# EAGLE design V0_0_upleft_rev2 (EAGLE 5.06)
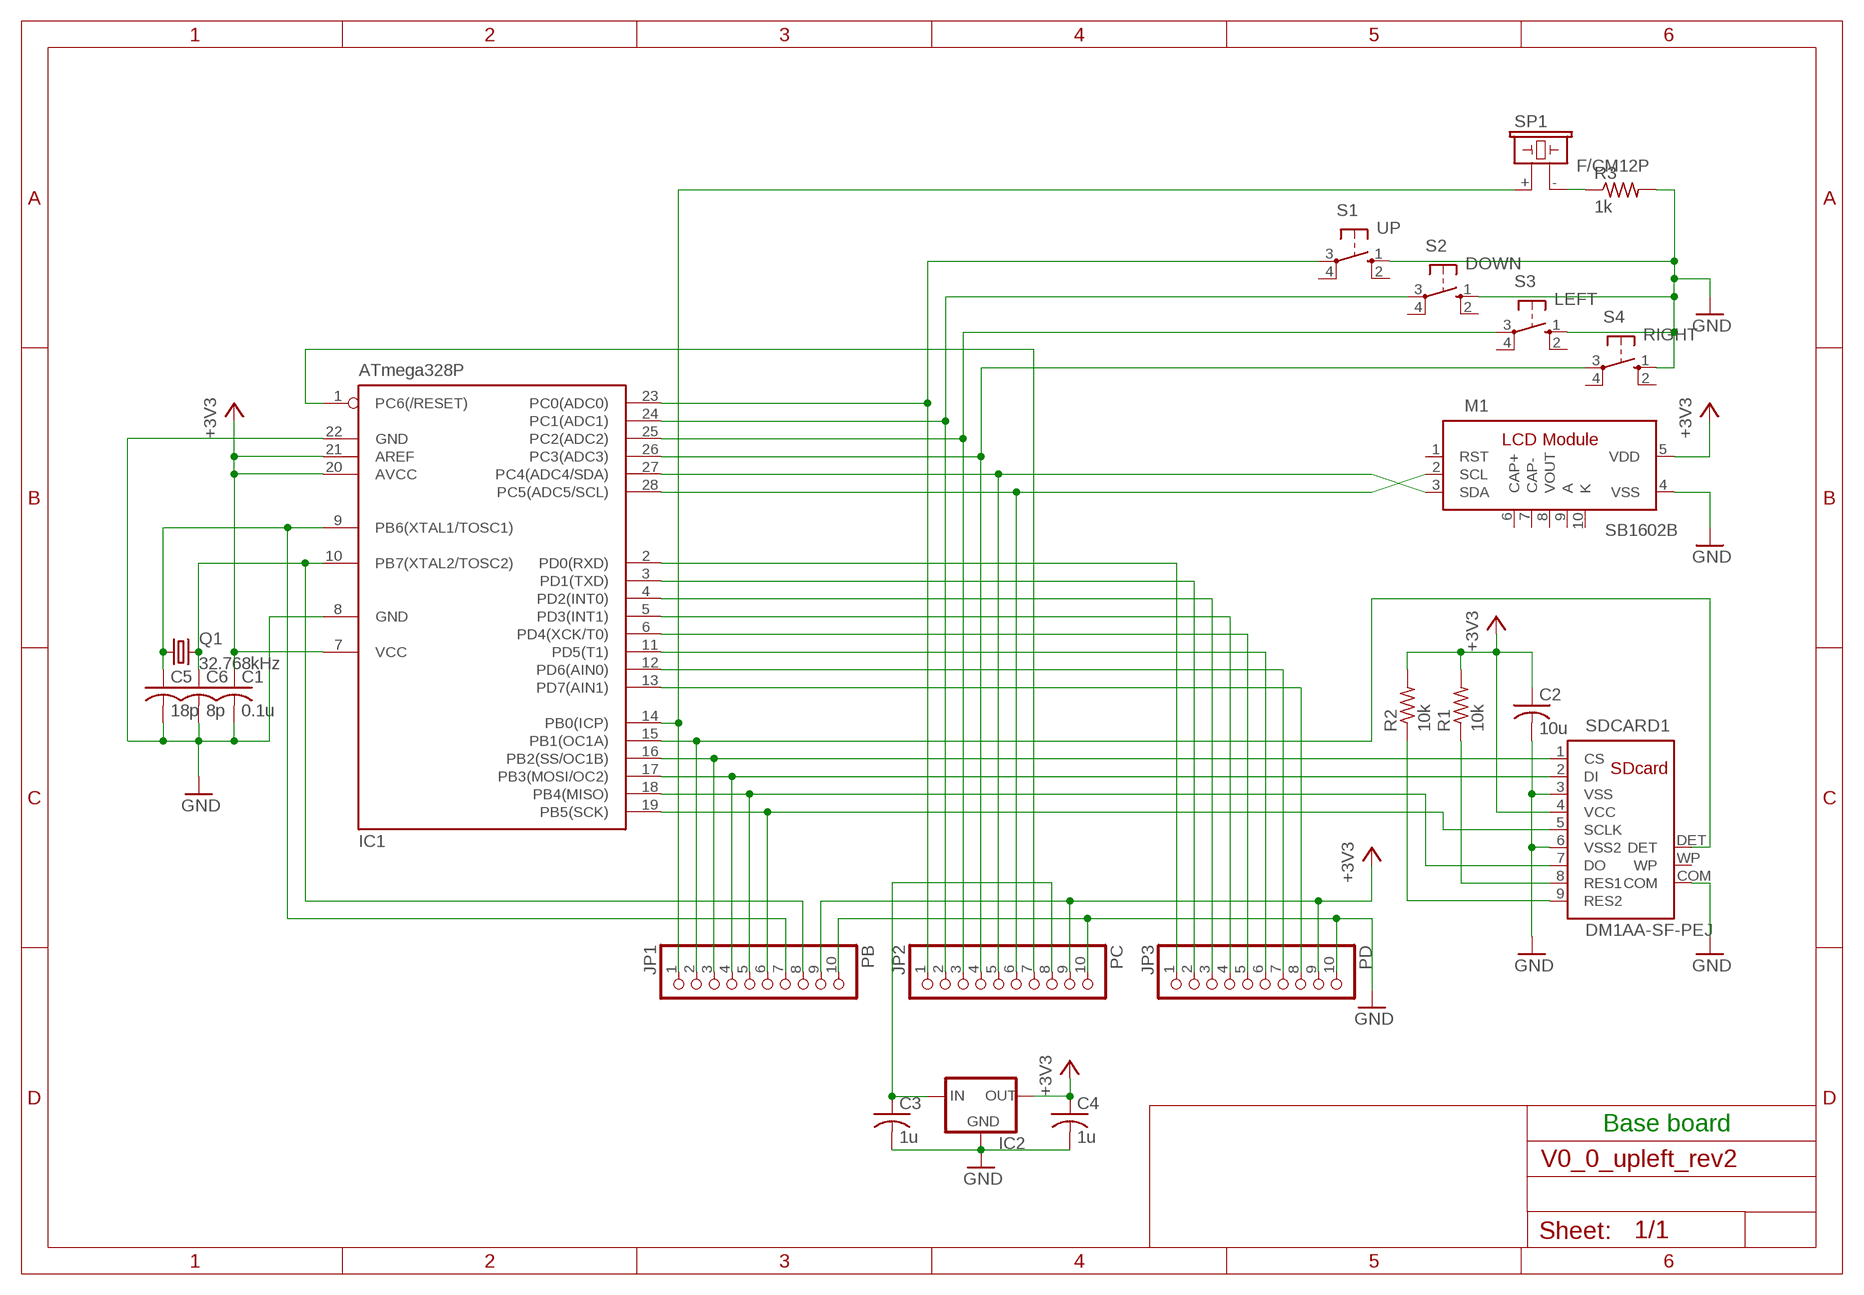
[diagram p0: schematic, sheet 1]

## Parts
C1  0.1u  C-US025-024X044  [C025-024X044]
C2  10u  C-US025-024X044  [C025-024X044]
C3  1u  C-US025-024X044  [C025-024X044]
C4  1u  C-US025-024X044  [C025-024X044]
C5  18p  C-US025-024X044  [C025-024X044]
C6  8p  C-US025-024X044  [C025-024X044]
IC1  ATmega328P  MEGA8-P  [DIL28-3]
IC2  XC63FPL  [TO92]
JP1  PB  PINHD-1X10  [1X10]
JP2  PC  PINHD-1X10  [1X10]
JP3  PD  PINHD-1X10  [1X10]
M1  SB1602B  [SB1602B]
Q1  32.768kHz  CRYSTALTC26H  [TC26H]
R1  10k  R-US_0204/5  [0204/5]
R2  10k  R-US_0204/5  [0204/5]
R3  1k  R-US_0204/5  [0204/5]
S1  UP  10-XX  [B3F-10XX]
S2  DOWN  10-XX  [B3F-10XX]
S3  LEFT  10-XX  [B3F-10XX]
S4  RIGHT  10-XX  [B3F-10XX]
SDCARD1  DM1AA-SF-PEJ  [DM1AA]
SP1  F/CM12P  [F/CM12P]

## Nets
+3V3: C1.1 C2.1 C4.1 IC1.7(VCC) IC1.20(AVCC) IC1.21(AREF) IC2.3(OUT) JP1.9 JP2.9 JP3.9 M1.5(VDD) R1.2 R2.2 SDCARD1.4(VCC)
GND: C1.2 C2.2 C3.2 C4.2 C5.2 C6.2 IC1.8(GND) IC1.22(GND) IC2.2(GND) JP1.10 JP2.10 JP3.10 M1.4(VSS) R3.2 S1.1(S) S2.1(S) S3.1(S) S4.1(S) SDCARD1.3(VSS) SDCARD1.6(VSS2) SDCARD1.COM
N$1: IC1.16(PB2(SS/OC1B)) JP1.3 SDCARD1.1(CS)
N$2: IC1.17(PB3(MOSI/OC2)) JP1.4 SDCARD1.2(DI)
N$3: IC1.18(PB4(MISO)) JP1.5 SDCARD1.7(DO)
N$4: IC1.19(PB5(SCK)) JP1.6 SDCARD1.5(SCLK)
N$5: IC1.27(PC4(ADC4/SDA)) JP2.5 M1.3(SDA)
N$6: IC1.28(PC5(ADC5/SCL)) JP2.6 M1.2(SCL)
N$7: IC1.2(PD0(RXD)) JP3.1
N$8: IC1.3(PD1(TXD)) JP3.2
N$9: R1.1 SDCARD1.8(RES1)
N$10: R2.1 SDCARD1.9(RES2)
N$11: IC1.4(PD2(INT0)) JP3.3
N$12: IC1.5(PD3(INT1)) JP3.4
N$13: IC1.6(PD4(XCK/T0)) JP3.5
N$14: IC1.11(PD5(T1)) JP3.6
N$15: IC1.12(PD6(AIN0)) JP3.7
N$16: IC1.13(PD7(AIN1)) JP3.8
N$17: R3.1 SP1.-
N$18: IC1.23(PC0(ADC0)) JP2.1 S1.3(P)
N$19: IC1.24(PC1(ADC1)) JP2.2 S2.3(P)
N$20: IC1.25(PC2(ADC2)) JP2.3 S3.3(P)
N$21: IC1.26(PC3(ADC3)) JP2.4 S4.3(P)
N$22: IC1.14(PB0(ICP)) JP1.1 SP1.+
N$23: IC1.15(PB1(OC1A)) JP1.2 SDCARD1.DET
N$24: C5.1 IC1.9(PB6(XTAL1/TOSC1)) JP1.7 Q1.1
N$26: IC1.1(PC6(/RESET)) JP2.7
N$27: C3.1 IC2.1(IN) JP2.8
N$28: C6.1 IC1.10(PB7(XTAL2/TOSC2)) JP1.8 Q1.2
Unconnected: M1.1(RST) M1.6(CAP+) M1.7(CAP-) M1.8(VOUT) S1.2(S1) S1.4(P1) S2.2(S1) S2.4(P1) S3.2(S1) S3.4(P1) S4.2(S1) S4.4(P1) SDCARD1.WP

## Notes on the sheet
- Base board

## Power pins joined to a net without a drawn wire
A: M1.9(A)
K: M1.10(K)

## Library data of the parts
C1-C6 = rcl:C-US: CAPACITOR, American symbol
IC1 = atmel:MEGA8-P: MICROCONTROLLER 8 Kbytes FLASH, 1 kbytes SRAM, 512 bytes EEPROM, USART, 4-channel 10 bit ADC, 2-channel 8 bit ADC Pin compatible with Atmega48, ATMega88, ATMega168 Source: avr.lbr
IC2 = v-reg:XC63FP: Positiv Voltage Regulators www.torex.co.jp/english/product/pro02/pdf/0201_xc62fp.pdf
JP1-JP3 = pinhead:PINHD-1X10: PIN HEADER
M1 = TOG:SB1602B: Strawberry Linux Co.,Ltd. I2C LCD Module Controler: ST7032i
Q1 = crystal:CRYSTAL: CRYSTAL
R1-R3 = rcl:R-US_: RESISTOR, American symbol
S1-S4 = switch-omron:10-XX: OMRON SWITCH
SDCARD1 = TOG:DM1AA-SF-PEJ: SDcard connector HIROSE
SP1 = buzzer:F/CM12P: BUZZER

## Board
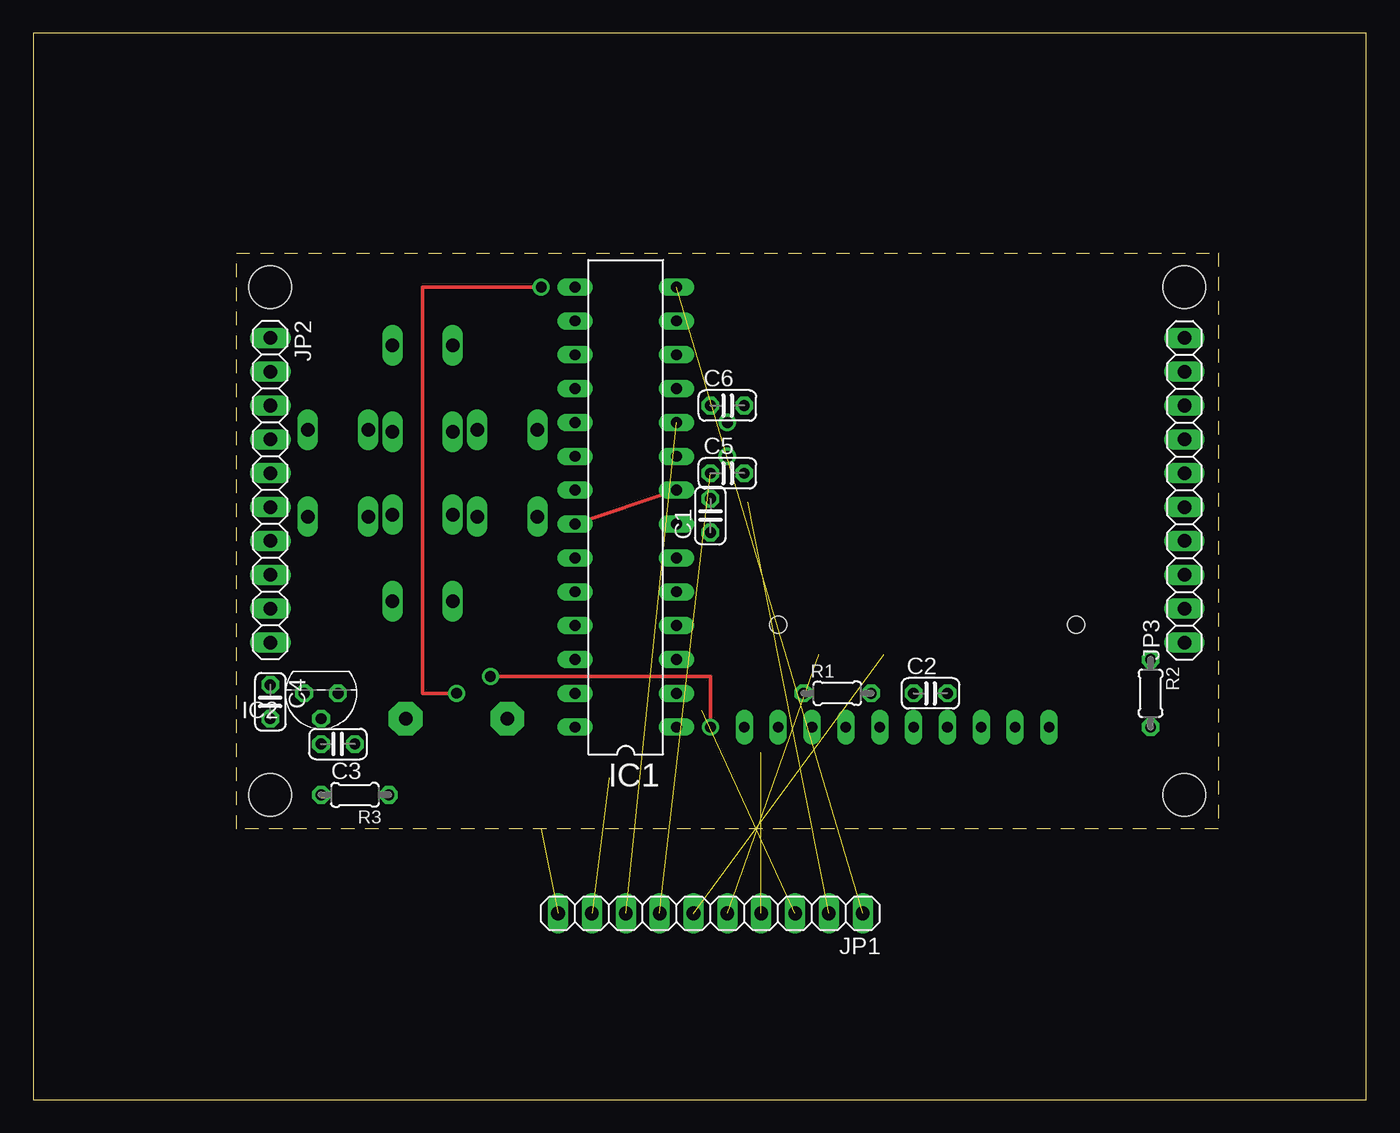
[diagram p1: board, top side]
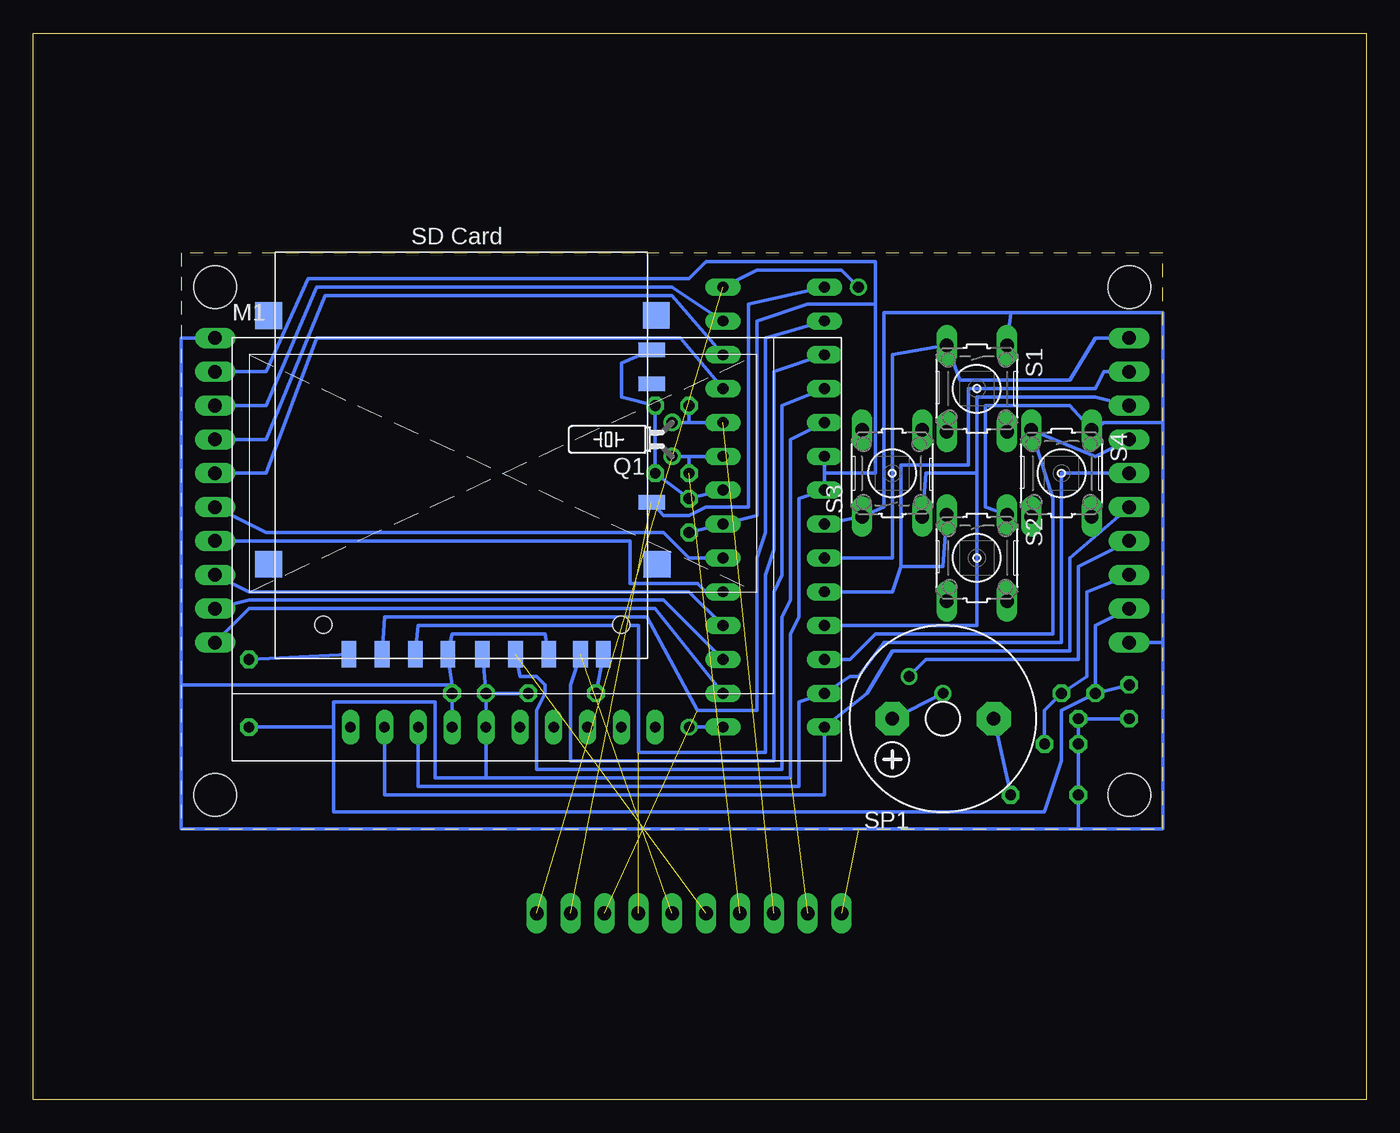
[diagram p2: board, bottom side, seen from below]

Size 100 x 80 mm. Coordinates in mm from the lower left corner, seen from the top.
Outline: 0,0 100,0 100,80 0,80 0,0
Outline: 15.24,63.5 88.9,63.5 88.9,20.32 15.24,20.32 15.24,63.5
Copper layers (1*16): Top 0.035mm / dielectric 1.5mm / Bottom 0.035mm
Design rules "default": minimum track width 10mil, minimum drill 24mil, track to track 8mil, track to pad 8mil, pad to pad 8mil, via to via 8mil, smd to smd 8mil, copper to edge 40mil, drill to drill 8mil, minimum pad ring 10mil, minimum via ring 8mil, stop-mask expansion 4mil, vias tented up to drill 0mil, thermal gap 10mil
Holes 3.2 mm at 17.78,60.96 86.36,60.96 86.36,22.86 17.78,22.86

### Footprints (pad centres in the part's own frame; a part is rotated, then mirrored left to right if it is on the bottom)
C025-024X044 = drill 0.813 octagon: 1 -1.27,0; 2 1.27,0
DIL28-3 = drill 0.813 long: 1 -16.51,-3.81; 2 -13.97,-3.81; 3 -11.43,-3.81; 4 -8.89,-3.81; 5 -6.35,-3.81; 6 -3.81,-3.81; 7 -1.27,-3.81; 8 1.27,-3.81; 9 3.81,-3.81; 10 6.35,-3.81; 11 8.89,-3.81; 12 11.43,-3.81; 13 13.97,-3.81; 14 16.51,-3.81; 15 16.51,3.81; 16 13.97,3.81; 17 11.43,3.81; 18 8.89,3.81; 19 6.35,3.81; 20 3.81,3.81; 21 1.27,3.81; 22 -1.27,3.81; 23 -3.81,3.81; 24 -6.35,3.81; 25 -8.89,3.81; 26 -11.43,3.81; 27 -13.97,3.81; 28 -16.51,3.81
TO92 = drill 0.813 octagon: 1 -1.27,0; 2 0,1.905; 3 1.27,0
1X10 = drill 1.016 long: 1 -11.43,0; 2 -8.89,0; 3 -6.35,0; 4 -3.81,0; 5 -1.27,0; 6 1.27,0; 7 3.81,0; 8 6.35,0; 9 8.89,0; 10 11.43,0
SB1602B = drill 0.8 long: 1 -13.97,-12.7; 2 -11.43,-12.7; 3 -8.89,-12.7; 4 -6.35,-12.7; 5 -3.81,-12.7; 6 -1.27,-12.7; 7 1.27,-12.7; 8 3.81,-12.7; 9 6.35,-12.7; 10 8.89,-12.7
TC26H = drill 0.813 round: 1 -1.27,0; 2 1.27,0
0204/5 = drill 0.813 octagon: 1 -2.54,0; 2 2.54,0
B3F-10XX = drill 1.016 long: 1 -3.251,2.261; 2 3.251,2.261; 3 -3.251,-2.261; 4 3.251,-2.261
DM1AA = smd 1.1 x 2: 1 3.98,14.22; 2 1.49,14.22; 3 -0.95,14.22; 4 -3.54,14.22; 5 -6.03,14.22; 6 -8.52,14.22; 7 -10.91,14.22; 8 -12.615,14.22; 9 6.47,14.22 | smd 2 x 1.1: COM -16.24,-8.62; DET -16.24,2.81; WP -16.24,-6.08 | smd 2.007 x 2.007: FG -16.64,7.455; P$13 12.5,7.455; P$14 12.5,-11.19; P$15 -16.59,-11.21 | hole 1.3: 8.39,12; -13.97,12
F/CM12P = drill 1.016 pad 2.54 octagon: + 3.81,0; - -3.81,0

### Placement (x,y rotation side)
C1  50.8,43.81 90 top
C2  67.31,30.48 0 top
C3  22.86,26.67 180 top
C4  17.78,29.84 270 top
C5  52.07,46.99 0 top
C6  52.07,52.07 0 top
IC1  44.45,44.45 90 top
IC2  21.59,30.48 180 top
JP1  50.8,13.97 180 top
JP2  17.78,45.72 270 top
JP3  86.36,45.72 90 top
M1  62.23,40.64 0 bottom
Q1  52.07,49.53 90 bottom
R1  60.33,30.48 0 top
R2  83.82,30.48 270 top
R3  24.13,22.86 180 top
S1  29.21,53.34 270 bottom
S2  29.21,40.64 270 bottom
S3  35.56,46.99 90 bottom
S4  22.86,46.99 270 bottom
SDCARD1  69.85,47.62 180 bottom
SP1  31.75,28.57 180 bottom

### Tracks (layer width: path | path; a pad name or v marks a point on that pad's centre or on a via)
+3V3  (1 unrouted)
  Bottom 0.254: IC2.3 20.32,35.56 JP2.9 | IC2.3 C4.1 | C1.1 IC1.7 45.72,43.81 45.72,58.42 41.91,59.69 36.83,59.69 | 40.64,46.99 IC1.21 42.55,45.09 42.55,36.2 43.18,34.92 43.18,24.13 66.04,24.13 | 40.64,46.99 IC1.20 | C2.1 SDCARD1.4 | C2.1 M1.5 66.04,24.13 | 36.83,59.69 36.83,46.99 40.64,46.99 | 66.04,24.13 69.85,24.13 69.85,29.84 77.47,29.84 77.47,27.94 | 77.47,27.94 77.47,21.59 24.13,21.59 22.86,25.4 22.86,29.21 IC2.3 | C2.1 R1.2 | 77.47,27.94 R2.2 | JP3.9 82.55,54.61 79.38,61.59 50.8,61.59 49.53,62.87 36.83,62.87 36.83,59.69
GND  (1 unrouted)
  Top 0.254: IC1.22 IC1.8
  Bottom 0.254: 88.9,31.11 88.9,20.32 38.1,20.32 21.59,20.32 | 88.9,31.11 88.9,57.15 JP3.10 | 21.59,20.32 15.24,20.32 15.24,34.29 | 15.24,34.29 15.24,50.8 | 15.24,50.8 15.24,59.05 26.67,59.05 | 26.67,59.05 36.2,59.05 36.2,44.45 S3.1 IC1.22 | 26.67,59.05 S1.1 | 15.24,50.8 19.68,50.8 S4.1 22.23,52.07 28.57,52.07 28.57,44.45 S2.1 | C4.2 IC2.2 C3.2 21.59,24.13 | 21.59,20.32 21.59,24.13 | 15.24,34.29 JP2.10 | IC1.8 C1.2 C5.2 C6.2 55.88,52.7 55.88,55.24 SDCARD1.COM | SDCARD1.6 61.59,34.92 68.58,34.92 SDCARD1.3 68.58,31.11 | M1.4 C2.2 68.58,31.11 | 88.9,31.11 68.58,31.11 | 21.59,24.13 R3.2
N$1  (1 unrouted)
  Bottom 0.254: IC1.16 45.09,57.15 45.09,42.55 45.72,40.64 45.72,29.21 50.16,29.21 53.98,36.2 73.66,36.2 SDCARD1.1
N$2  (1 unrouted)
  Bottom 0.254: IC1.17 44.45,54.61 44.45,41.27 45.09,39.37 45.09,26.04 54.61,26.04 54.61,35.56 71.12,35.56 SDCARD1.2
N$3  (1 unrouted)
  Bottom 0.254: IC1.18 43.81,52.07 43.81,39.37 44.45,38.1 44.45,25.4 59.69,25.4 59.69,31.11 SDCARD1.7
N$4  (1 unrouted)
  Bottom 0.254: IC1.19 43.18,49.53 43.18,37.47 43.81,36.2 43.81,24.77 62.23,24.77 62.23,29.21 61.59,30.48 61.59,31.11 62.23,31.75 63.5,31.75 SDCARD1.5
N$5
  Bottom 0.254: JP2.5 22.86,46.99 22.86,34.29 36.2,34.29 38.1,31.75 38.73,31.75 IC1.27 42.55,29.84 42.55,23.5 71.12,23.5 M1.3
N$6
  Bottom 0.254: JP2.6 22.23,40.64 22.23,33.66 35.56,33.66 37.47,30.48 IC1.28 40.64,22.86 73.66,22.86 M1.2
N$7
  Bottom 0.254: IC1.2 53.34,36.83 83.82,36.83 JP3.1
N$8
  Bottom 0.254: IC1.3 52.7,37.47 83.82,37.47 JP3.2
N$9
  Bottom 0.254: R1.1 SDCARD1.8
N$10
  Bottom 0.254: SDCARD1.9 R2.1
N$11
  Bottom 0.254: IC1.4 50.8,38.1 83.82,38.1 JP3.3
N$12
  Bottom 0.254: IC1.5 49.53,38.1 50.16,38.73 55.24,38.73 55.24,41.91 JP3.4
N$13
  Bottom 0.254: IC1.6 50.8,40.64 52.7,42.55 82.55,42.55 JP3.5
N$14
  Bottom 0.254: IC1.11 51.44,57.15 78.74,57.15 82.55,46.99 JP3.6
N$15
  Bottom 0.254: IC1.12 52.07,60.33 78.11,60.33 82.55,49.53 JP3.7
N$16
  Bottom 0.254: IC1.13 52.07,60.96 78.74,60.96 82.55,52.07 JP3.8
N$17
  Bottom 0.254: R3.1 SP1.-
N$18
  Bottom 0.254: IC1.23 35.56,40.64 35.56,55.88 S1.3 30.48,53.98 22.23,53.98 20.32,57.15 JP2.1
N$19
  Bottom 0.254: S2.3 31.75,40.01 34.92,40.01 | 34.92,40.01 35.56,38.1 IC1.24 | JP2.2 19.68,54.61 20.32,53.34 29.84,53.34 29.84,47.62 34.92,47.62 34.92,40.01
N$20
  Bottom 0.254: IC1.25 29.21,35.56 29.21,46.99 | JP2.3 20.32,52.7 29.21,52.7 29.21,46.99 | 29.21,46.99 33.02,46.99 S3.3
N$21
  Bottom 0.254: JP2.4 20.32,48.26 S4.3 23.5,45.09 23.5,34.92 36.83,34.92 38.73,33.02 IC1.26
N$22  (via drill 0.8 pad 1.27)  (1 unrouted)
  Top 0.254: v31.75,30.48 29.21,30.48 29.21,60.96 v38.1,60.96
  Bottom 0.254: v31.75,30.48 SP1.+ | v38.1,60.96 39.37,62.23 45.72,62.23 IC1.14
N$23  (1 unrouted)
  Bottom 0.254: IC1.15 46.35,59.69 46.35,44.45 49.53,44.45 50.8,43.81 52.7,43.81 SDCARD1.DET
N$24  (1 unrouted)
  Bottom 0.254: 50.8,48.26 IC1.9 | 50.8,48.26 Q1.1 | C5.1 50.8,48.26
N$26  (via drill 0.8 pad 1.27)
  Top 0.254: v34.29,31.75 50.8,31.75 v50.8,27.94
  Bottom 0.254: v34.29,31.75 33.02,33.02 21.59,33.02 21.59,40.01 JP2.7 | v50.8,27.94 IC1.1
N$27
  Bottom 0.254: JP2.8 20.95,38.1 20.95,31.75 IC2.1 24.13,29.21 C3.1
N$28  (1 unrouted)
  Bottom 0.254: IC1.10 50.8,50.8 | 50.8,50.8 Q1.2 | 50.8,50.8 C6.1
